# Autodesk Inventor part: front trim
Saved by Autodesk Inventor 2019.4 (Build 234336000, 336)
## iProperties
Created: 2020-09
Part Number: front trim
Material: Generic
Document SubType Name: Modeling
Designer: Administrator
Density: 1 g/cm^3
Appearance: Default
Title: front trim
Author: Administrator
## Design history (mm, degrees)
feature "Body1"
body "Solid1"
